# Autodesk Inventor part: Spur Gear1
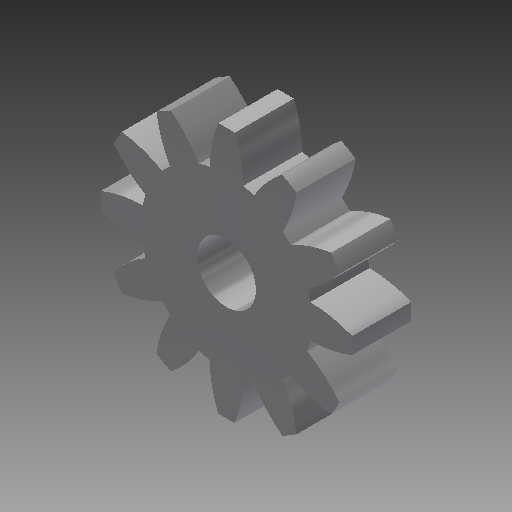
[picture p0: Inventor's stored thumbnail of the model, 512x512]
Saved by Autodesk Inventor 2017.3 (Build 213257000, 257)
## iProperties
Created: 2020-03
Part Number: Spur Gear1
Material: Steel
Document SubType Name: Modeling
Designer: Tim_G
Categories: <?xml version="1.0" encoding="UTF-16"?> <MemberInstance><Categories><FamilyTemplate><FamilyTemplateParameter ValueType="xs:double" Id="1" ObjectReferenceKey="da
Density: 1 g/cm^3
Appearance: Steel
CustomPartVersion: 1
Author: Tim_G
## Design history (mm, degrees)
sketch "Sketch1"
  geometry: C1 r 10.661 at (0, 0)
  constraints: 1 centre point
  dimensions: "d0" = 21.3211 diameter of C1 (= da_da)
extrude "Extrusion1" new body sketch "Sketch1" distance "d1" = 5 (= da_b); taper "d2" = 0 deg
workplane "Work Plane2"
sketch "Sketch2"
  geometry: C1 r 10.661 at (0, 0) reference; C2 r 9.138 at (0, 0)
  constraints: 1 centre point, 1 coincident
  dimensions: "d3" = 18.27523 diameter of C2 (= da_dw)
feature "Pitch Diameter" sketch "Sketch2" dims "d4" = 10, "d5" = 0
workplane "Work Plane8"
workplane "Work Plane9"
feature "Spur Gear" dims "d4" = 10, "da_b" = 5, "da_d" = 18.27523, "da_aw" = 25.12844, "da_da" = 21.3211, "da_df" = 14.46789, "da_dw" = 18.27523, angle "da_beta" = 0 deg, "da_lefttooth" = 0, "da_righttooth" = 0
sketch "Sketch3"
  geometry: C1 r 2.5 at (0, 0); 1 further point
  constraints: 1 centre point, 1 coincident
  dimensions: "d49" = 5 diameter of C1
extrude "Extrusion2" cut sketch "Sketch3" distance "d50" = 5; taper "d51" = 0 deg
body "Solid1"
body "Srf1"
other parameters: "d16" = 25.12844 (= da_aw), "d17" = 0, "d34" = 15 deg (computed from da_z), "d39" = 0, "d41" = 0, "d43" = 25.12844 (= da_aw), "d46" = 25.12844 (= da_aw), "d47" = 0, "d48" = 0
